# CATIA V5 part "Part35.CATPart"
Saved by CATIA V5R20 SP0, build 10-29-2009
Part number: 9TS2008M8
Revision: ANY
Definition: UNKNOWN
Nomenclature: 9TS2008M8
Source: Unknown
Bounding box of the stored display mesh (mm): x -10 to 10, y -10 to 10, z 0 to 8
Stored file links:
  C:\Users\Utente\Desktop\IO LAVORO\3D X SITO CF\CUMSA\3D files GR\GR 465050-10\Part35.CATPart
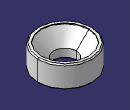
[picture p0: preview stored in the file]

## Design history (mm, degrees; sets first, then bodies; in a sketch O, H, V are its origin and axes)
Body1 "Chaflán1" (main body)
  Solid1: solid without history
